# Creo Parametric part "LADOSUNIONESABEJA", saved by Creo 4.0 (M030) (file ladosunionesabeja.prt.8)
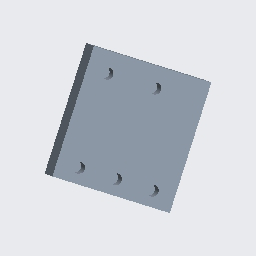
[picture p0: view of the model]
Units: millimeter Newton Second (mmNs); MM, TONNE, SECS

Created from: MMNS_PART_SOLID.PRT

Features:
  1. datum plane "RIGHT"
  2. datum plane "TOP"
  3. datum plane "FRONT"
  4. coordinate system
  5. sketch "Sketch 1"
  6. extrusion "Extrude 1"
  7. pattern "Pattern 1"
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
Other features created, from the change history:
  hole "Hole 1"
  hole "Hole 1 [2]"
  hole "Hole 1 [3]"
  hole "Hole 2"
  pattern "Patrón 2"
  hole "Taladro 2 [2]"
  hole "Hole 3"
  pattern "Pattern 3"
  hole "Hole 3 [2]"

Surfaces: 13 plane, 7 cylinder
